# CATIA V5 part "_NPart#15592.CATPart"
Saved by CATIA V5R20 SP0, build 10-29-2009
Part number: 1BOLAØ2,3
Revision: ANY
Definition: UNKNOWN
Nomenclature: 1BOLAØ2,3
Source: Unknown
Bounding box of the stored display mesh (mm): x -1.19 to 1.19, y -1.19 to 1.19, z -1.19 to 1.19
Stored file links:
  C:\Users\Utente\Desktop\IO LAVORO\3D X SITO CF\CUMSA\3D files AE\AE 052430\_NPart#15592.CATPart
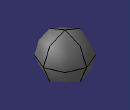
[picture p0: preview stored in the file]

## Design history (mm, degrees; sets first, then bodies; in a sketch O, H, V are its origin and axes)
Body1 "Revolución1" (main body)
  Solid1: solid without history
